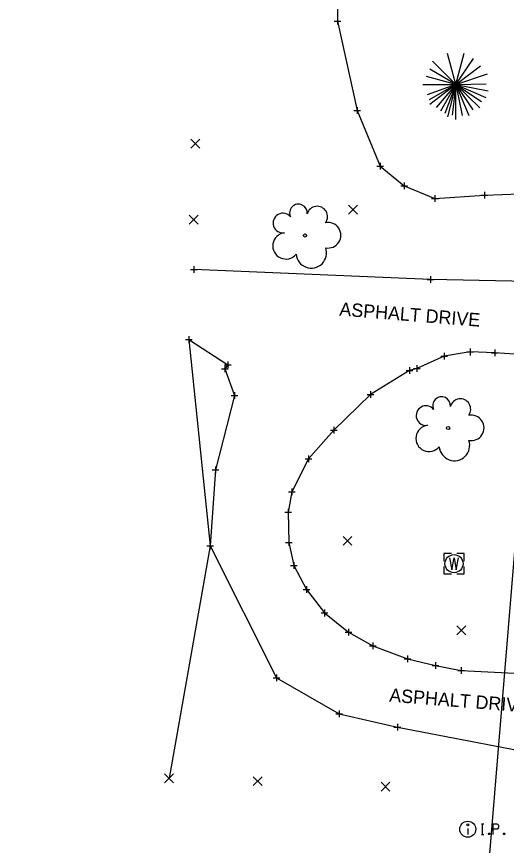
# Model space of a CAD drawing. Extents: x 1380440 to 1381945, y 468756 to 470369.
# Drawn here: x 1381467.5 to 1381540.8, y 469561.9 to 469686 of the extents above; entities that cross this region are included whole.
import ezdxf

# ---------------------------------------------------------------- set-up
doc = ezdxf.new("R2010")
doc.units = 0
for name, color, linetype in [('DR_P_Storm_Sewer', 7, 'Continuous'), ('GE_P_Driveway_CL', 7, 'Continuous'), ('RW_P_Const_Limits', 7, 'Continuous'), ('RW_X_Esmt_SH', 7, 'Continuous'), ('SC_Scratch1', 7, 'Continuous'), ('SC_Scratch10', 7, 'Continuous'), ('SH_Named_Boundary', 7, 'Continuous'), ('UT_X_Gas', 7, 'Continuous'), ('X-SUBDIVISION', 7, 'Continuous'), ('XS_X_Ground_Line', 7, 'Continuous')]:
    doc.layers.add(name, color=color, linetype=linetype)

msp = doc.modelspace()

# ---------------------------------------------------------------- linework, layer by layer
at = {"layer": 'DR_P_Storm_Sewer'}
msp.add_lwpolyline([(1381553.61, 469681.87), (1381554.59, 469697.85), (1381554.02, 469701.13), (1381552.9, 469703.26), (1381550.42, 469704.97), (1381547.1, 469705.7), (1381540.46, 469707.05), (1381528.05, 469707.71), (1381525.41, 469706.81), (1381521.51, 469704.5), (1381517.2, 469699.24), (1381515.42, 469695.13), (1381515.51, 469685.3), (1381518.45, 469671.91), (1381521.91, 469663.58), (1381525.51, 469660.65), (1381530.1, 469658.77), (1381537.53, 469659.25), (1381542.81, 469659.47), (1381547.18, 469661.79), (1381552.24, 469676.73)], close=True, dxfattribs=at)
at = {"layer": 'GE_P_Driveway_CL'}
for p, q in [((1381493.58, 469666.3), (1381494.92, 469667.64)), ((1381493.58, 469667.64), (1381494.92, 469666.3)), ((1381517.19, 469656.4), (1381518.53, 469657.73)), ((1381517.19, 469657.73), (1381518.53, 469656.4)), ((1381493.34, 469654.93), (1381494.67, 469656.27)), ((1381493.34, 469656.27), (1381494.67, 469654.93)), ((1381516.36, 469606.85), (1381517.69, 469608.19)), ((1381516.36, 469608.19), (1381517.69, 469606.85)), ((1381533.38, 469593.47), (1381534.71, 469594.81)), ((1381533.38, 469594.81), (1381534.71, 469593.47)), ((1381489.65, 469571.32), (1381490.98, 469572.66)), ((1381489.65, 469572.66), (1381490.98, 469571.32)), ((1381502.92, 469570.88), (1381504.25, 469572.22)), ((1381502.92, 469572.22), (1381504.25, 469570.88)), ((1381522.04, 469570.06), (1381523.38, 469571.4)), ((1381522.04, 469571.4), (1381523.38, 469570.06))]:
    msp.add_line(p, q, dxfattribs=at)
at = {"layer": 'RW_P_Const_Limits'}
msp.add_line((1381532.96, 469604.1), (1381532.96, 469604.1), dxfattribs=at)
for points in [[(1381532.56, 469605.6), (1381531.46, 469605.6), (1381531.46, 469604.5)], [(1381532.29, 469605), (1381532.62, 469603.2), (1381532.96, 469605), (1381533.29, 469603.2), (1381533.62, 469605)], [(1381534.46, 469604.5), (1381534.46, 469605.6), (1381533.36, 469605.6)], [(1381531.46, 469603.7), (1381531.46, 469602.6), (1381532.56, 469602.6)], [(1381533.36, 469602.6), (1381534.46, 469602.6), (1381534.46, 469603.7)]]:
    msp.add_lwpolyline(points, dxfattribs=at)
msp.add_circle((1381532.96, 469604.1), 1.35, dxfattribs=at)
at = {"layer": 'RW_X_Esmt_SH'}
for points in [[(1381560.13, 469652.11), (1381557.13, 469649.61), (1381554.25, 469646.66), (1381551.36, 469646.16), (1381529.45, 469646.65), (1381494.05, 469648.13)], [(1381493.3, 469637.64), (1381499.12, 469633.84), (1381498.69, 469633.28), (1381500.11, 469629.25), (1381497.25, 469618.13), (1381496.48, 469606.75), (1381506.38, 469587.01), (1381515.78, 469581.64), (1381524.48, 469579.62), (1381546.37, 469575.44), (1381550.51, 469573.39), (1381551.89, 469572.26), (1381552.82, 469570.44), (1381553.19, 469568.93), (1381553.66, 469569.19)], [(1381550.65, 469634.88), (1381539.08, 469635.65), (1381535.36, 469635.78), (1381531.51, 469635.15), (1381527.42, 469633.31), (1381526.3, 469633.03), (1381520.45, 469629.44), (1381514.98, 469624.1), (1381511.2, 469619.77), (1381508.71, 469614.84), (1381508.13, 469611.79), (1381508.23, 469607.25), (1381509.01, 469603.81), (1381510.9, 469600.22), (1381513.57, 469596.72), (1381517.17, 469593.84), (1381520.79, 469591.82), (1381525.98, 469589.85), (1381530.17, 469588.84), (1381534.01, 469588.12), (1381547.01, 469587.49)]]:
    msp.add_lwpolyline(points, dxfattribs=at)
at = {"layer": 'SC_Scratch1'}
msp.add_line((1381535.02, 469564.48), (1381535.02, 469563.59), dxfattribs=at)
for points in [[(1381537.06, 469565.16), (1381537.41, 469565.16)], [(1381537.23, 469563.56), (1381537.23, 469565.16)], [(1381538.8, 469563.56), (1381538.8, 469565.16), (1381539.33, 469565.16), (1381539.38, 469565.15), (1381539.46, 469565.12), (1381539.49, 469565.1), (1381539.52, 469565.07), (1381539.57, 469565.01), (1381539.6, 469564.95), (1381539.62, 469564.85), (1381539.62, 469564.7), (1381539.61, 469564.64), (1381539.59, 469564.57), (1381539.55, 469564.48), (1381539.5, 469564.44), (1381539.47, 469564.42), (1381539.41, 469564.39), (1381539.33, 469564.38), (1381538.8, 469564.38)], [(1381538.19, 469563.78), (1381538.25, 469563.78), (1381538.28, 469563.75), (1381538.31, 469563.7), (1381538.31, 469563.64), (1381538.28, 469563.59), (1381538.25, 469563.56), (1381538.19, 469563.56), (1381538.16, 469563.59), (1381538.12, 469563.64), (1381538.12, 469563.7), (1381538.16, 469563.75), (1381538.19, 469563.78)], [(1381540.44, 469563.78), (1381540.49, 469563.78), (1381540.53, 469563.75), (1381540.56, 469563.7), (1381540.56, 469563.64), (1381540.53, 469563.59), (1381540.49, 469563.56), (1381540.44, 469563.56), (1381540.41, 469563.59), (1381540.37, 469563.64), (1381540.37, 469563.7), (1381540.41, 469563.75), (1381540.44, 469563.78)], [(1381537.06, 469563.56), (1381537.41, 469563.56)]]:
    msp.add_lwpolyline(points, dxfattribs=at)
for centre, radius in [((1381535.02, 469564.36), 1.2), ((1381535.02, 469565.01), 0.16)]:
    msp.add_circle(centre, radius, dxfattribs=at)
at = {"layer": 'SC_Scratch10'}
for p, q in [((1381533.24, 469675.82), (1381532, 469680.44)), ((1381533.24, 469675.82), (1381534.5, 469680.52)), ((1381533.24, 469675.82), (1381529.75, 469679.31)), ((1381533.24, 469675.82), (1381535.89, 469679.71)), ((1381533.24, 469675.82), (1381529.33, 469678.12)), ((1381533.24, 469675.82), (1381536.9, 469678.63)), ((1381533.24, 469675.82), (1381528.83, 469677.01)), ((1381533.24, 469675.82), (1381537.98, 469677.43)), ((1381528.3, 469675.82), (1381533.24, 469675.82)), ((1381533.24, 469675.82), (1381528.95, 469674.26)), ((1381533.24, 469675.82), (1381529.26, 469673.54)), ((1381533.24, 469675.82), (1381529.33, 469672.83)), ((1381533.24, 469675.82), (1381530.29, 469672.36)), ((1381533.24, 469675.82), (1381530.92, 469671.81)), ((1381533.24, 469675.82), (1381531.57, 469671.48)), ((1381533.24, 469675.82), (1381531.98, 469670.97)), ((1381533.24, 469675.82), (1381532.7, 469671.23)), ((1381533.24, 469675.82), (1381537.75, 469675.92)), ((1381533.24, 469670.58), (1381533.24, 469675.82)), ((1381533.24, 469675.82), (1381534.16, 469671.19)), ((1381533.24, 469675.82), (1381535.17, 469671.16)), ((1381533.24, 469675.82), (1381535.78, 469672.03)), ((1381533.24, 469675.82), (1381536.83, 469672.3)), ((1381533.24, 469675.82), (1381537.06, 469673.27)), ((1381533.24, 469675.82), (1381537.7, 469673.88)), ((1381533.24, 469675.82), (1381538.07, 469674.87))]:
    msp.add_line(p, q, dxfattribs=at)
for centre in [(1381510.66, 469653.21), (1381532.08, 469624.4)]:
    msp.add_circle(centre, 0.24, dxfattribs=at)
for centre, radius, start, end in [((1381509.68, 469656.58), 1.32, 354.0047, 205.9741), ((1381512.49, 469656.04), 1.55, 323.83, 165.0376), ((1381507.35, 469655.08), 1.47, 39.0625, 279.5412), ((1381514.12, 469653.25), 1.91, 259.1453, 101.4596), ((1381507.81, 469651.66), 1.97, 96.1722, 320.5737), ((1381511.61, 469650.61), 2.28, 184.9476, 19.4572), ((1381531.1, 469627.76), 1.32, 354.0047, 205.9741), ((1381533.91, 469627.22), 1.55, 323.83, 165.0376), ((1381528.77, 469626.26), 1.47, 39.0625, 279.5412), ((1381535.54, 469624.43), 1.91, 259.1453, 101.4596), ((1381529.23, 469622.85), 1.97, 96.1722, 320.5737), ((1381533.03, 469621.79), 2.28, 184.9476, 19.4572)]:
    msp.add_arc(centre, radius, start, end, dxfattribs=at)
at = {"layer": 'SH_Named_Boundary'}
for p, q in [((1381515.01, 469685.3), (1381516.01, 469685.3)), ((1381515.51, 469685.8), (1381515.51, 469684.8)), ((1381515.51, 469685.3), (1381515.51, 469685.3)), ((1381517.95, 469671.91), (1381518.95, 469671.91)), ((1381518.45, 469672.41), (1381518.45, 469671.41)), ((1381518.45, 469671.91), (1381518.45, 469671.91)), ((1381521.41, 469663.58), (1381522.41, 469663.58)), ((1381521.91, 469664.08), (1381521.91, 469663.08)), ((1381521.91, 469663.58), (1381521.91, 469663.58)), ((1381525.01, 469660.65), (1381526.01, 469660.65)), ((1381525.51, 469661.15), (1381525.51, 469660.15)), ((1381525.51, 469660.65), (1381525.51, 469660.65)), ((1381530.1, 469659.27), (1381530.1, 469658.27)), ((1381537.03, 469659.25), (1381538.03, 469659.25)), ((1381537.53, 469659.75), (1381537.53, 469658.75)), ((1381537.53, 469659.25), (1381537.53, 469659.25)), ((1381529.6, 469658.77), (1381530.6, 469658.77)), ((1381530.1, 469658.77), (1381530.1, 469658.77)), ((1381493.55, 469648.13), (1381494.55, 469648.13)), ((1381494.05, 469648.63), (1381494.05, 469647.63)), ((1381494.05, 469648.13), (1381494.05, 469648.13)), ((1381529.45, 469647.15), (1381529.45, 469646.15)), ((1381528.95, 469646.65), (1381529.95, 469646.65)), ((1381529.45, 469646.65), (1381529.45, 469646.65)), ((1381493.3, 469638.14), (1381493.3, 469637.14)), ((1381492.8, 469637.64), (1381493.8, 469637.64)), ((1381493.3, 469637.64), (1381493.3, 469637.64)), ((1381531.51, 469635.65), (1381531.51, 469634.65)), ((1381534.86, 469635.78), (1381535.86, 469635.78)), ((1381535.36, 469636.28), (1381535.36, 469635.28)), ((1381535.36, 469635.78), (1381535.36, 469635.78)), ((1381538.58, 469635.65), (1381539.58, 469635.65)), ((1381539.08, 469636.15), (1381539.08, 469635.15)), ((1381539.08, 469635.65), (1381539.08, 469635.65)), ((1381499.12, 469634.34), (1381499.12, 469633.34)), ((1381531.01, 469635.15), (1381532.01, 469635.15)), ((1381531.51, 469635.15), (1381531.51, 469635.15)), ((1381498.19, 469633.28), (1381499.19, 469633.28)), ((1381498.62, 469633.84), (1381499.62, 469633.84)), ((1381498.69, 469633.78), (1381498.69, 469632.78)), ((1381498.69, 469633.28), (1381498.69, 469633.28)), ((1381499.12, 469633.84), (1381499.12, 469633.84)), ((1381526.3, 469633.53), (1381526.3, 469632.53)), ((1381526.92, 469633.31), (1381527.92, 469633.31)), ((1381527.42, 469633.81), (1381527.42, 469632.81)), ((1381527.42, 469633.31), (1381527.42, 469633.31)), ((1381525.8, 469633.03), (1381526.8, 469633.03)), ((1381526.3, 469633.03), (1381526.3, 469633.03)), ((1381500.11, 469629.75), (1381500.11, 469628.75)), ((1381519.95, 469629.44), (1381520.95, 469629.44)), ((1381520.45, 469629.94), (1381520.45, 469628.94)), ((1381520.45, 469629.44), (1381520.45, 469629.44)), ((1381499.61, 469629.25), (1381500.61, 469629.25)), ((1381500.11, 469629.25), (1381500.11, 469629.25)), ((1381514.98, 469624.6), (1381514.98, 469623.6)), ((1381514.48, 469624.1), (1381515.48, 469624.1)), ((1381514.98, 469624.1), (1381514.98, 469624.1)), ((1381510.7, 469619.77), (1381511.7, 469619.77)), ((1381511.2, 469620.27), (1381511.2, 469619.27)), ((1381511.2, 469619.77), (1381511.2, 469619.77)), ((1381497.25, 469618.63), (1381497.25, 469617.63)), ((1381497.25, 469618.63), (1381497.25, 469617.63)), ((1381496.75, 469618.13), (1381497.75, 469618.13)), ((1381496.75, 469618.13), (1381497.75, 469618.13)), ((1381497.25, 469618.13), (1381497.25, 469618.13)), ((1381497.25, 469618.13), (1381497.25, 469618.13)), ((1381508.21, 469614.84), (1381509.21, 469614.84)), ((1381508.71, 469615.34), (1381508.71, 469614.34)), ((1381508.71, 469614.84), (1381508.71, 469614.84)), ((1381508.13, 469612.29), (1381508.13, 469611.29)), ((1381507.63, 469611.79), (1381508.63, 469611.79)), ((1381508.13, 469611.79), (1381508.13, 469611.79)), ((1381496.48, 469607.25), (1381496.48, 469606.25)), ((1381507.73, 469607.25), (1381508.73, 469607.25)), ((1381508.23, 469607.75), (1381508.23, 469606.75)), ((1381508.23, 469607.25), (1381508.23, 469607.25)), ((1381495.98, 469606.75), (1381496.98, 469606.75)), ((1381496.48, 469606.75), (1381496.48, 469606.75)), ((1381508.51, 469603.81), (1381509.51, 469603.81)), ((1381509.01, 469604.31), (1381509.01, 469603.31)), ((1381509.01, 469603.81), (1381509.01, 469603.81)), ((1381510.4, 469600.22), (1381511.4, 469600.22)), ((1381510.9, 469600.72), (1381510.9, 469599.72)), ((1381510.9, 469600.22), (1381510.9, 469600.22)), ((1381513.57, 469597.22), (1381513.57, 469596.22)), ((1381513.07, 469596.72), (1381514.07, 469596.72)), ((1381513.57, 469596.72), (1381513.57, 469596.72)), ((1381516.67, 469593.84), (1381517.67, 469593.84)), ((1381517.17, 469594.34), (1381517.17, 469593.34)), ((1381517.17, 469593.84), (1381517.17, 469593.84)), ((1381520.79, 469592.32), (1381520.79, 469591.32)), ((1381520.29, 469591.82), (1381521.29, 469591.82)), ((1381520.79, 469591.82), (1381520.79, 469591.82)), ((1381525.48, 469589.85), (1381526.48, 469589.85)), ((1381525.98, 469590.35), (1381525.98, 469589.35)), ((1381525.98, 469589.85), (1381525.98, 469589.85)), ((1381529.67, 469588.84), (1381530.67, 469588.84)), ((1381530.17, 469589.34), (1381530.17, 469588.34)), ((1381530.17, 469588.84), (1381530.17, 469588.84)), ((1381534.01, 469588.62), (1381534.01, 469587.62)), ((1381506.38, 469587.51), (1381506.38, 469586.51)), ((1381506.38, 469587.51), (1381506.38, 469586.51)), ((1381533.51, 469588.12), (1381534.51, 469588.12)), ((1381534.01, 469588.12), (1381534.01, 469588.12)), ((1381505.88, 469587.01), (1381506.88, 469587.01)), ((1381505.88, 469587.01), (1381506.88, 469587.01)), ((1381506.38, 469587.01), (1381506.38, 469587.01)), ((1381506.38, 469587.01), (1381506.38, 469587.01)), ((1381515.28, 469581.64), (1381516.28, 469581.64)), ((1381515.78, 469582.14), (1381515.78, 469581.14)), ((1381515.78, 469581.64), (1381515.78, 469581.64)), ((1381524.48, 469580.12), (1381524.48, 469579.12)), ((1381523.98, 469579.62), (1381524.98, 469579.62)), ((1381524.48, 469579.62), (1381524.48, 469579.62))]:
    msp.add_line(p, q, dxfattribs=at)
at = {"layer": 'UT_X_Gas'}
msp.add_lwpolyline([(1381485.9, 468926.41), (1381594.27, 470237.89), (1380558, 470279.29)], dxfattribs=at)
at = {"layer": 'XS_X_Ground_Line'}
msp.add_lwpolyline([(1381493.3, 469637.64), (1381496.48, 469606.75), (1381490.32, 469571.99)], dxfattribs=at)

# ---------------------------------------------------------------- texts
at = {"layer": 'X-SUBDIVISION'}
for p in [(1381515.76, 469641.24), (1381523.22, 469583.46)]:
    msp.add_text('ASPHALT DRIVE', height=2, rotation=355.4428, dxfattribs=at).set_placement(p)

doc.saveas('drawing.dxf')
